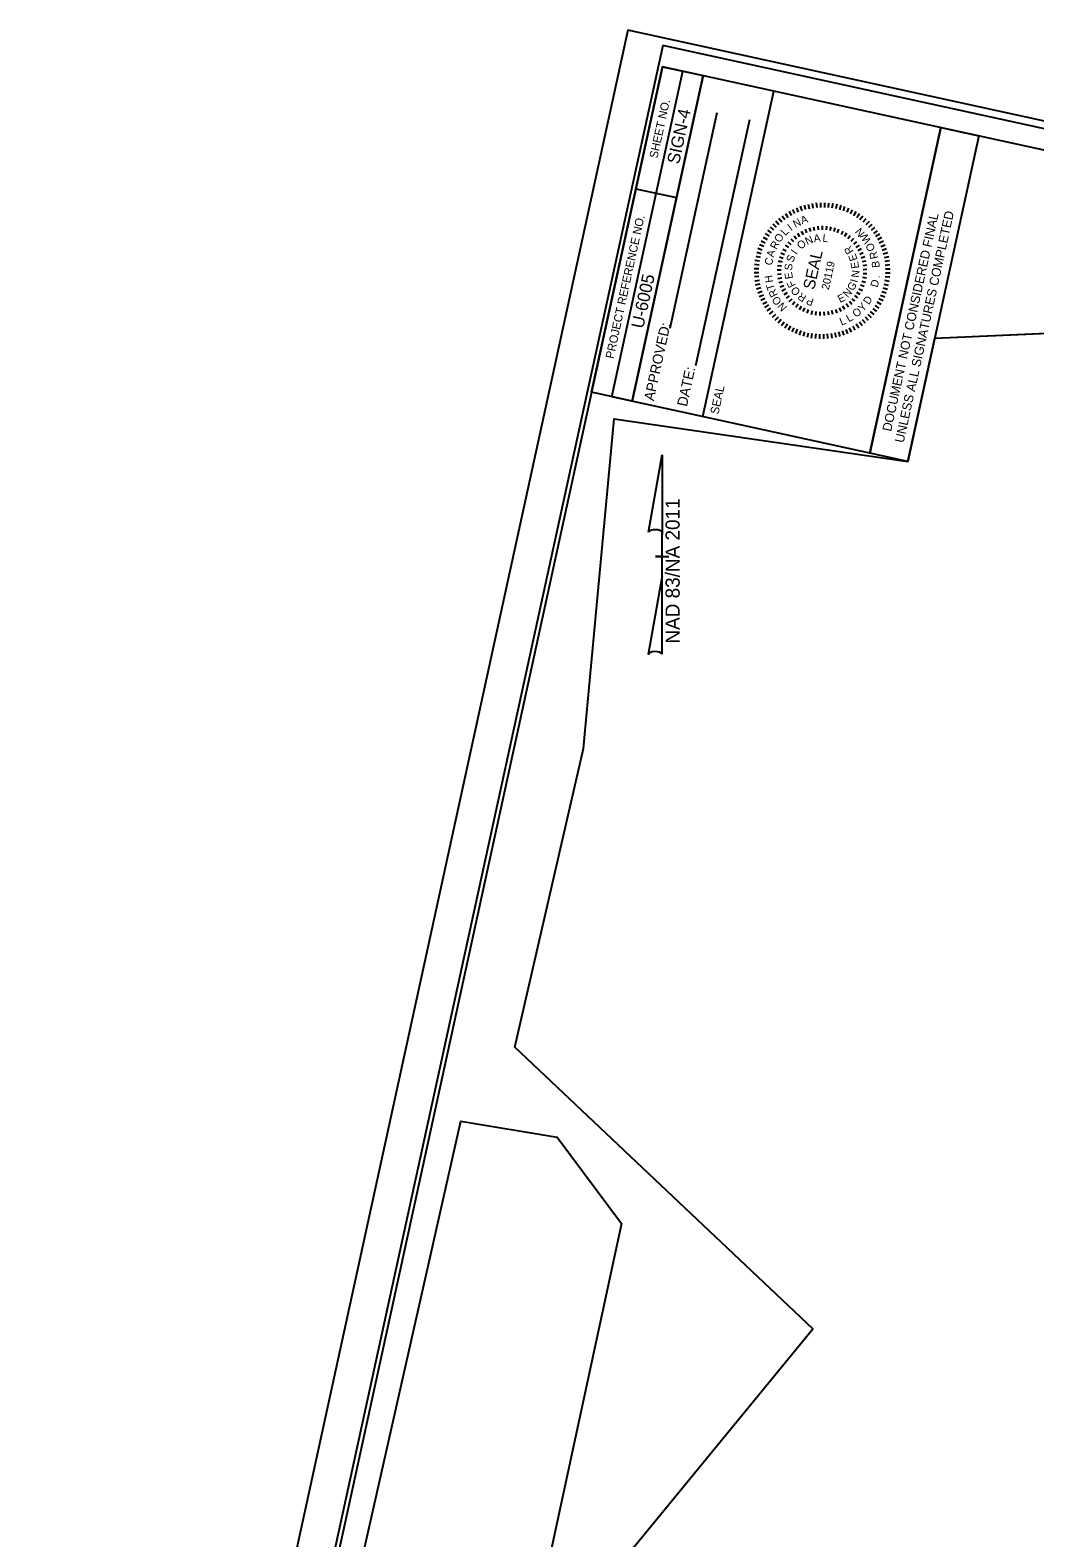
# Model space of a CAD drawing. Extents: x 1615829 to 1617263, y 900664 to 902544.
# Drawn here: x 1615829 to 1616433, y 901639 to 902544 of the extents above; entities that cross this region are included whole.
import ezdxf

# ---------------------------------------------------------------- set-up
doc = ezdxf.new("R2010")
doc.units = 0
for name, color, linetype in [('CTL Primary Horizontal and Vertical CELL', 7, 'Continuous'), ('CTL Primary Horizontal and Vertical Cogo Number', 7, 'Continuous'), ('CTL Secondary Horizontal and Vertical CELL', 7, 'Continuous'), ('CTL Secondary Horizontal and Vertical Cogo Number', 7, 'Continuous'), ('Default', 7, 'Continuous'), ('Exist DTM Crownline Cogo Number', 7, 'Continuous'), ('Exist Roads Curbs Cogo Point CELL', 7, 'Continuous'), ('Exist Roads EOT Cogo Number', 7, 'Continuous'), ('Exist Structure Minor Catch Basin Cogo Number', 7, 'Continuous'), ('Exist Structure Minor Pipes CMP 15 Inch Cogo Number', 7, 'Continuous'), ('Exist Structure Minor Pipes RCP 18 Inch Cogo Number', 7, 'Continuous'), ('Exist Structure Minor Pipes RCP 18 Inch Cogo Point CELL', 7, 'Continuous')]:
    doc.layers.add(name, color=color, linetype=linetype)

msp = doc.modelspace()

# ---------------------------------------------------------------- linework, layer by layer
at = {"layer": 'CTL Primary Horizontal and Vertical CELL'}
msp.add_lwpolyline([(1616208.96, 902534.66), (1615853.55, 900906.5), (1616884.38, 900681.48), (1617239.79, 902309.64)], close=True, dxfattribs=at)
at = {"layer": 'CTL Primary Horizontal and Vertical Cogo Number'}
msp.add_lwpolyline([(1616187.99, 902543.84), (1615828.85, 900898.58), (1616903.54, 900663.99), (1617262.68, 902309.25)], close=True, dxfattribs=at)
at = {"layer": 'CTL Secondary Horizontal and Vertical CELL'}
for p, q in [((1616178.38, 902323.78), (1616221.05, 902519.22)), ((1616190.6, 902321.11), (1616233.26, 902516.56)), ((1616190.6, 902321.11), (1616233.26, 902516.56)), ((1616192.84, 902448.61), (1616217.27, 902443.28))]:
    msp.add_line(p, q, dxfattribs=at)
for points in [[(1616208.79, 902521.9), (1615888.89, 901056.41), (1616914.73, 900832.48), (1617234.63, 902297.97)], [(1616166.12, 902326.45), (1616208.79, 902521.9), (1616233.26, 902516.56), (1616190.6, 902321.11)]]:
    msp.add_lwpolyline(points, close=True, dxfattribs=at)
at = {"layer": 'Default'}
for p, q in [((1616282.67, 902433.81), (1616284.17, 902431.46)), ((1616284.79, 902435.08), (1616286.15, 902432.64)), ((1616286.98, 902436.21), (1616288.19, 902433.7)), ((1616289.24, 902437.22), (1616290.29, 902434.64)), ((1616291.55, 902438.08), (1616292.45, 902435.44)), ((1616293.91, 902438.8), (1616294.65, 902436.11)), ((1616296.31, 902439.38), (1616296.88, 902436.65)), ((1616298.74, 902439.82), (1616299.15, 902437.06)), ((1616301.19, 902440.1), (1616301.43, 902437.32)), ((1616303.66, 902440.24), (1616303.73, 902437.45)), ((1616306.13, 902440.23), (1616306.03, 902437.44)), ((1616308.59, 902440.06), (1616308.33, 902437.29)), ((1616311.04, 902439.75), (1616310.61, 902437)), ((1616313.47, 902439.3), (1616312.87, 902436.58)), ((1616315.86, 902438.69), (1616315.1, 902436.01)), ((1616318.22, 902437.95), (1616317.3, 902435.32)), ((1616320.52, 902437.06), (1616319.44, 902434.49)), ((1616322.77, 902436.04), (1616321.54, 902433.54)), ((1616324.95, 902434.88), (1616323.57, 902432.46)), ((1616327.06, 902433.59), (1616325.53, 902431.26)), ((1616273.42, 902425.7), (1616275.55, 902423.9)), ((1616275.07, 902427.54), (1616277.09, 902425.62)), ((1616276.82, 902429.28), (1616278.72, 902427.24)), ((1616278.68, 902430.9), (1616280.45, 902428.76)), ((1616280.63, 902432.42), (1616282.27, 902430.17)), ((1616294.5, 902424.32), (1616295.39, 902422.17)), ((1616296.96, 902425.18), (1616297.63, 902422.96)), ((1616299.49, 902425.81), (1616299.94, 902423.53)), ((1616302.06, 902426.19), (1616302.29, 902423.87)), ((1616304.66, 902426.32), (1616304.67, 902423.99)), ((1616307.26, 902426.19), (1616307.04, 902423.88)), ((1616309.84, 902425.82), (1616309.4, 902423.54)), ((1616312.37, 902425.2), (1616311.71, 902422.98)), ((1616313.88, 902422.22), (1616314.74, 902424.37)), ((1616329.08, 902432.18), (1616327.42, 902429.94)), ((1616331.02, 902430.65), (1616329.22, 902428.51)), ((1616332.86, 902429), (1616330.94, 902426.98)), ((1616334.59, 902427.24), (1616332.56, 902425.35)), ((1616336.22, 902425.39), (1616334.07, 902423.62)), ((1616267.01, 902415.2), (1616269.57, 902414.13)), ((1616268.03, 902417.45), (1616270.53, 902416.22)), ((1616269.19, 902419.63), (1616271.61, 902418.25)), ((1616270.48, 902421.74), (1616272.81, 902420.21)), ((1616271.89, 902423.76), (1616274.13, 902422.1)), ((1616284.08, 902416.72), (1616285.86, 902415.23)), ((1616285.85, 902418.63), (1616287.48, 902416.97)), ((1616287.8, 902420.36), (1616289.26, 902418.55)), ((1616289.91, 902421.89), (1616291.18, 902419.95)), ((1616292.15, 902423.22), (1616293.23, 902421.16)), ((1616317.19, 902423.24), (1616316.11, 902421.19)), ((1616319.43, 902421.93), (1616318.16, 902419.98)), ((1616321.54, 902420.4), (1616320.09, 902418.59)), ((1616323.49, 902418.68), (1616321.87, 902417.01)), ((1616325.27, 902416.77), (1616323.49, 902415.27)), ((1616337.74, 902423.44), (1616335.48, 902421.8)), ((1616339.13, 902421.4), (1616336.78, 902419.9)), ((1616340.39, 902419.28), (1616337.96, 902417.92)), ((1616341.53, 902417.09), (1616339.02, 902415.88)), ((1616264.77, 902408.15), (1616267.49, 902407.55)), ((1616265.37, 902410.55), (1616268.05, 902409.79)), ((1616266.12, 902412.9), (1616268.75, 902411.98)), ((1616279.06, 902407.67), (1616281.27, 902406.96)), ((1616279.98, 902410.11), (1616282.11, 902409.18)), ((1616281.13, 902412.44), (1616283.17, 902411.32)), ((1616282.5, 902414.66), (1616284.42, 902413.34)), ((1616326.85, 902414.7), (1616324.94, 902413.38)), ((1616328.22, 902412.5), (1616326.19, 902411.36)), ((1616329.38, 902410.16), (1616327.25, 902409.23)), ((1616330.3, 902407.73), (1616328.1, 902407.01)), ((1616342.53, 902414.83), (1616339.96, 902413.78)), ((1616343.4, 902412.52), (1616340.76, 902411.62)), ((1616344.12, 902410.16), (1616341.43, 902409.42)), ((1616344.7, 902407.76), (1616341.97, 902407.19)), ((1616263.83, 902398.34), (1616266.61, 902398.41)), ((1616263.84, 902400.81), (1616266.63, 902400.71)), ((1616264.01, 902403.27), (1616266.78, 902403.01)), ((1616264.31, 902405.72), (1616267.07, 902405.29)), ((1616277.76, 902400), (1616280.08, 902399.94)), ((1616277.82, 902397.4), (1616280.14, 902397.56)), ((1616277.95, 902402.59), (1616280.25, 902402.31)), ((1616278.38, 902405.16), (1616280.65, 902404.66)), ((1616280.65, 902404.66), (1616278.38, 902405.16)), ((1616330.99, 902405.22), (1616328.72, 902404.71)), ((1616331.43, 902402.65), (1616329.13, 902402.37)), ((1616331.56, 902397.45), (1616329.25, 902397.62)), ((1616331.62, 902400.06), (1616329.3, 902400)), ((1616345.14, 902405.33), (1616342.38, 902404.92)), ((1616345.42, 902402.88), (1616342.64, 902402.64)), ((1616345.54, 902397.94), (1616342.76, 902398.04)), ((1616345.56, 902400.41), (1616342.77, 902400.34)), ((1616263.96, 902395.87), (1616266.75, 902396.11)), ((1616264.25, 902393.43), (1616267.01, 902393.83)), ((1616264.69, 902390.99), (1616267.41, 902391.56)), ((1616265.26, 902388.59), (1616267.95, 902389.33)), ((1616278.14, 902394.81), (1616280.43, 902395.2)), ((1616278.71, 902392.27), (1616280.95, 902392.88)), ((1616279.51, 902389.79), (1616281.69, 902390.62)), ((1616280.56, 902387.41), (1616282.64, 902388.44)), ((1616326.77, 902388.48), (1616328.85, 902387.45)), ((1616329.89, 902389.85), (1616327.72, 902390.67)), ((1616330.7, 902392.33), (1616328.45, 902392.93)), ((1616331.26, 902394.87), (1616328.97, 902395.26)), ((1616344.01, 902388.2), (1616341.33, 902388.96)), ((1616344.62, 902390.6), (1616341.89, 902391.2)), ((1616345.07, 902393.03), (1616342.32, 902393.46)), ((1616345.38, 902395.48), (1616342.61, 902395.74)), ((1616265.99, 902386.23), (1616268.63, 902387.13)), ((1616266.85, 902383.92), (1616269.43, 902384.97)), ((1616267.85, 902381.66), (1616270.36, 902382.87)), ((1616268.99, 902379.47), (1616271.42, 902380.83)), ((1616270.26, 902377.35), (1616272.61, 902378.85)), ((1616281.83, 902385.14), (1616283.8, 902386.36)), ((1616283.31, 902383), (1616285.15, 902384.41)), ((1616284.98, 902381.01), (1616286.69, 902382.59)), ((1616286.85, 902379.19), (1616288.39, 902380.93)), ((1616288.88, 902377.56), (1616290.25, 902379.44)), ((1616320.55, 902377.6), (1616319.18, 902379.48)), ((1616322.58, 902379.23), (1616321.04, 902380.97)), ((1616324.44, 902381.05), (1616322.74, 902382.63)), ((1616326.12, 902383.04), (1616324.27, 902384.45)), ((1616327.6, 902385.19), (1616325.62, 902386.41)), ((1616340.2, 902379.12), (1616337.77, 902380.5)), ((1616341.36, 902381.3), (1616338.86, 902382.53)), ((1616342.38, 902383.55), (1616339.81, 902384.62)), ((1616343.26, 902385.85), (1616340.64, 902386.77)), ((1616271.65, 902375.31), (1616273.9, 902376.95)), ((1616273.17, 902373.36), (1616275.31, 902375.13)), ((1616274.79, 902371.51), (1616276.83, 902373.4)), ((1616276.53, 902369.75), (1616278.45, 902371.77)), ((1616278.37, 902368.1), (1616280.16, 902370.24)), ((1616291.06, 902376.14), (1616292.23, 902378.14)), ((1616293.37, 902374.93), (1616294.34, 902377.04)), ((1616295.78, 902373.95), (1616296.54, 902376.14)), ((1616298.28, 902373.21), (1616298.83, 902375.46)), ((1616300.83, 902372.71), (1616301.16, 902375.01)), ((1616303.42, 902372.47), (1616303.53, 902374.78)), ((1616306.03, 902372.47), (1616305.91, 902374.78)), ((1616308.62, 902372.72), (1616308.28, 902375.02)), ((1616311.17, 902373.23), (1616310.61, 902375.48)), ((1616313.66, 902373.97), (1616312.89, 902376.16)), ((1616316.07, 902374.95), (1616315.09, 902377.06)), ((1616318.38, 902376.17), (1616317.2, 902378.17)), ((1616330.71, 902367.85), (1616328.93, 902369.99)), ((1616332.56, 902369.47), (1616330.67, 902371.51)), ((1616334.32, 902371.21), (1616332.3, 902373.13)), ((1616335.97, 902373.05), (1616333.83, 902374.85)), ((1616337.49, 902374.99), (1616335.26, 902376.65)), ((1616338.91, 902377.01), (1616336.58, 902378.54)), ((1616280.31, 902366.57), (1616281.97, 902368.81)), ((1616282.33, 902365.16), (1616283.86, 902367.49)), ((1616284.44, 902363.87), (1616285.82, 902366.29)), ((1616286.62, 902362.71), (1616287.85, 902365.21)), ((1616288.87, 902361.69), (1616289.94, 902364.26)), ((1616291.17, 902360.8), (1616292.09, 902363.43)), ((1616293.52, 902360.06), (1616294.28, 902362.74)), ((1616295.92, 902359.45), (1616296.52, 902362.17)), ((1616298.35, 902359), (1616298.78, 902361.75)), ((1616300.79, 902358.69), (1616301.06, 902361.46)), ((1616303.26, 902358.52), (1616303.36, 902361.31)), ((1616305.72, 902358.51), (1616305.66, 902361.3)), ((1616308.19, 902358.65), (1616307.96, 902361.43)), ((1616310.64, 902358.93), (1616310.24, 902361.69)), ((1616313.07, 902359.37), (1616312.51, 902362.1)), ((1616315.47, 902359.95), (1616314.74, 902362.64)), ((1616317.84, 902360.67), (1616316.94, 902363.31)), ((1616320.15, 902361.54), (1616319.1, 902364.11)), ((1616322.4, 902362.54), (1616321.2, 902365.05)), ((1616324.6, 902363.68), (1616323.24, 902366.11)), ((1616326.72, 902364.94), (1616325.22, 902367.29)), ((1616328.75, 902366.33), (1616327.12, 902368.58))]:
    msp.add_line(p, q, dxfattribs=at)
at = {"layer": 'Exist DTM Crownline Cogo Number'}
msp.add_lwpolyline([(1616850.42, 902379.94), (1617227.49, 902296.2), (1617121.36, 901790.43), (1617088.18, 901641.75), (1617042.44, 901522.26), (1617032.35, 901430.63), (1617021.35, 901334.38), (1616928.77, 900896.77), (1615902.83, 901120.28), (1615974.27, 901386.7), (1616087.67, 901888.92), (1616145.49, 901879.24), (1616184.12, 901827.49), (1616138.37, 901614.97), (1616150.59, 901618.07), (1616181.32, 901620.66), (1616299.19, 901764.2), (1616120.07, 901933.32), (1616161.35, 902112.51), (1616179.69, 902310.42), (1616356.27, 902284.95), (1616372.44, 902359.01)], close=True, dxfattribs=at)
at = {"layer": 'Exist Roads Curbs Cogo Point CELL'}
msp.add_line((1616372.44, 902359.01), (1616856.51, 902380.51), dxfattribs=at)
at = {"layer": 'Exist Roads EOT Cogo Number'}
msp.add_lwpolyline([(1616333.32, 902289.96), (1616375.98, 902485.4), (1616398.93, 902480.39), (1616356.27, 902284.95)], close=True, dxfattribs=at)
at = {"layer": 'Exist Structure Minor Catch Basin Cogo Number'}
for p, q in [((1616200.34, 902242.5), (1616208.54, 902288.85)), ((1616208.59, 902288.85), (1616208.54, 902288.85)), ((1616208.59, 902288.85), (1616208.54, 902288.85)), ((1616208.59, 902288.85), (1616208.59, 902241.05)), ((1616208.59, 902216.25), (1616208.59, 902242.45)), ((1616208.59, 902241.05), (1616208.59, 902242.4)), ((1616204.59, 902227.85), (1616204.54, 902227.85)), ((1616208.14, 902227.85), (1616204.59, 902227.85)), ((1616204.64, 902227.85), (1616212.64, 902227.85)), ((1616208.59, 902216.25), (1616200.24, 902169)), ((1616208.64, 902169.2), (1616208.59, 902216.25))]:
    msp.add_line(p, q, dxfattribs=at)
for centre, start_param, end_param in [((1616204.47, 902242), 0.216388, 2.908219), ((1616204.47, 902168.83), 0.201328, 3.141593)]:
    msp.add_ellipse(centre, major_axis=(4.23, -0.03), ratio=0.461098, start_param=start_param, end_param=end_param, dxfattribs=at)
at = {"layer": 'Exist Structure Minor Pipes CMP 15 Inch Cogo Number'}
for p, q in [((1616213.43, 902364.94), (1616241.71, 902494.5)), ((1616228.89, 902342.44), (1616261.16, 902490.26))]:
    msp.add_line(p, q, dxfattribs=at)
at = {"layer": 'Exist Structure Minor Pipes RCP 18 Inch Cogo Point CELL'}
for p, q in [((1616233.02, 902311.85), (1616275.68, 902507.3)), ((1616375.98, 902485.4), (1616333.32, 902289.96)), ((1616224.48, 902313.71), (1616178.38, 902323.78)), ((1616333.32, 902289.96), (1616224.48, 902313.71))]:
    msp.add_line(p, q, dxfattribs=at)

# ---------------------------------------------------------------- texts
at = {"layer": 'CTL Secondary Horizontal and Vertical CELL'}
for s, height, p in [('SHEET NO.', 5, (1616205.72, 902466.58)), ('PROJECT REFERENCE NO.', 5.0001, (1616179.36, 902346.29))]:
    msp.add_text(s, height=height, rotation=77.68623, dxfattribs=at).set_placement(p)
at = {"layer": 'CTL Secondary Horizontal and Vertical Cogo Number'}
for s, p in [('SIGN-4', (1616218.71, 902463.02)), ('U-6005', (1616197.21, 902364.31))]:
    msp.add_text(s, height=7.5, rotation=77.68623, dxfattribs=at).set_placement(p)
at = {"layer": 'Default'}
for s, height, rotation, p in [('L', 4.64, 46.75696, (1616282.57, 902420.1)), ('I', 4.64, 37.18148, (1616286, 902423.17)), ('N', 4.64, 27.88702, (1616288.64, 902424.98)), ('A', 4.64, 18.11949, (1616292.64, 902427.23)), ('N', 4.64, 129.80945, (1616330.54, 902422.12)), ('R', 4.64, 62.95005, (1616277.27, 902411.83)), ('O', 4.64, 59.89324, (1616279.54, 902415.93)), ('O', 4.64, 39.36178, (1616291.86, 902411.9)), ('N', 4.64, 24.06553, (1616295.67, 902414.73)), ('A', 4.64, 8.76929, (1616299.92, 902416.4)), ('L', 4.64, 353.47304, (1616304.73, 902416.88)), ('W', 4.64, 120.92682, (1616334.27, 902417.31)), ('O', 4.64, 112.04419, (1616336.69, 902412.11)), ('C', 4.64, 74.95936, (1616274.36, 902402.24)), ('A', 4.64, 74.95936, (1616275.54, 902407.17)), ('S', 4.64, 69.95427, (1616287.26, 902404.03)), ('I', 4.64, 54.65803, (1616289.3, 902408.64)), ('SEAL', 6.965, 77.6024, (1616299.97, 902387.64)), ('R', 4.64, 122.16728, (1616323.82, 902411.08)), ('E', 4.64, 108.3962, (1616326.03, 902406.07)), ('R', 4.64, 103.22158, (1616338.4, 902407.01)), ('E', 4.64, 100.54676, (1616287.26, 902394.83)), ('S', 4.64, 85.25052, (1616286.64, 902399.42)), ('20119', 4.64, 77.6024, (1616308.72, 902387.66)), ('E', 4.64, 98.41032, (1616326.94, 902401)), ('N', 4.64, 83.01825, (1616326.69, 902395.03)), ('B', 4.64, 94.21901, (1616339.31, 902401.33)), ('H', 4.64, 98.67005, (1616275.29, 902392.58)), ('T', 4.64, 108.102, (1616276.47, 902388.5)), ('R', 4.64, 116.26296, (1616278.33, 902384.9)), ('F', 4.64, 115.84301, (1616289.03, 902390.64)), ('O', 4.64, 131.13926, (1616292.02, 902386.82)), ('N', 4.64, 48.52756, (1616320.13, 902382.95)), ('G', 4.64, 57.29379, (1616323.23, 902386.91)), ('I', 4.64, 75.38859, (1616325.87, 902391.99)), ('D', 4.64, 73.69235, (1616337.95, 902389.05)), ('.', 4.64, 81.4347, (1616339.24, 902394.76)), ('O', 4.64, 129.31969, (1616280.66, 902380.94)), ('N', 4.64, 131.27912, (1616283.92, 902377.5)), ('R', 4.64, 146.4355, (1616295.7, 902384.13)), ('P', 4.64, 161.73175, (1616300.04, 902382.46)), ('E', 4.64, 27.67249, (1616315.52, 902379.97)), ('Y', 4.64, 46.92456, (1616329.17, 902374.49)), ('D', 4.64, 55.89704, (1616332.77, 902378.64)), ('L', 4.64, 21.53741, (1616316.27, 902366.45)), ('L', 4.64, 29.60922, (1616320.78, 902368.4)), ('O', 4.64, 38.25197, (1616325.11, 902371.06))]:
    msp.add_text(s, height=height, rotation=rotation, dxfattribs=at).set_placement(p)
at = {"layer": 'Exist Roads EOT Cogo Number'}
for s, p in [('DOCUMENT NOT CONSIDERED FINAL', (1616346.16, 902302.58)), ('UNLESS ALL SIGNATURES COMPLETED', (1616353.67, 902295.75))]:
    msp.add_text(s, height=5.4984, rotation=77.68623, dxfattribs=at).set_placement(p)
at = {"layer": 'Exist Structure Minor Catch Basin Cogo Number'}
msp.add_text('NAD 83/NA 2011', height=8.5, rotation=90, dxfattribs=at).set_placement((1616219.11, 902175.54))
at = {"layer": 'Exist Structure Minor Pipes CMP 15 Inch Cogo Number'}
msp.add_text('SEAL', height=5.094, rotation=77.68116, dxfattribs=at).set_placement((1616242.37, 902312.91))
at = {"layer": 'Exist Structure Minor Pipes RCP 18 Inch Cogo Number'}
for s, p in [('APPROVED:', (1616203.55, 902320.93)), ('DATE:', (1616223.42, 902317.53))]:
    msp.add_text(s, height=6.11, rotation=77.68116, dxfattribs=at).set_placement(p)

doc.saveas('drawing.dxf')
